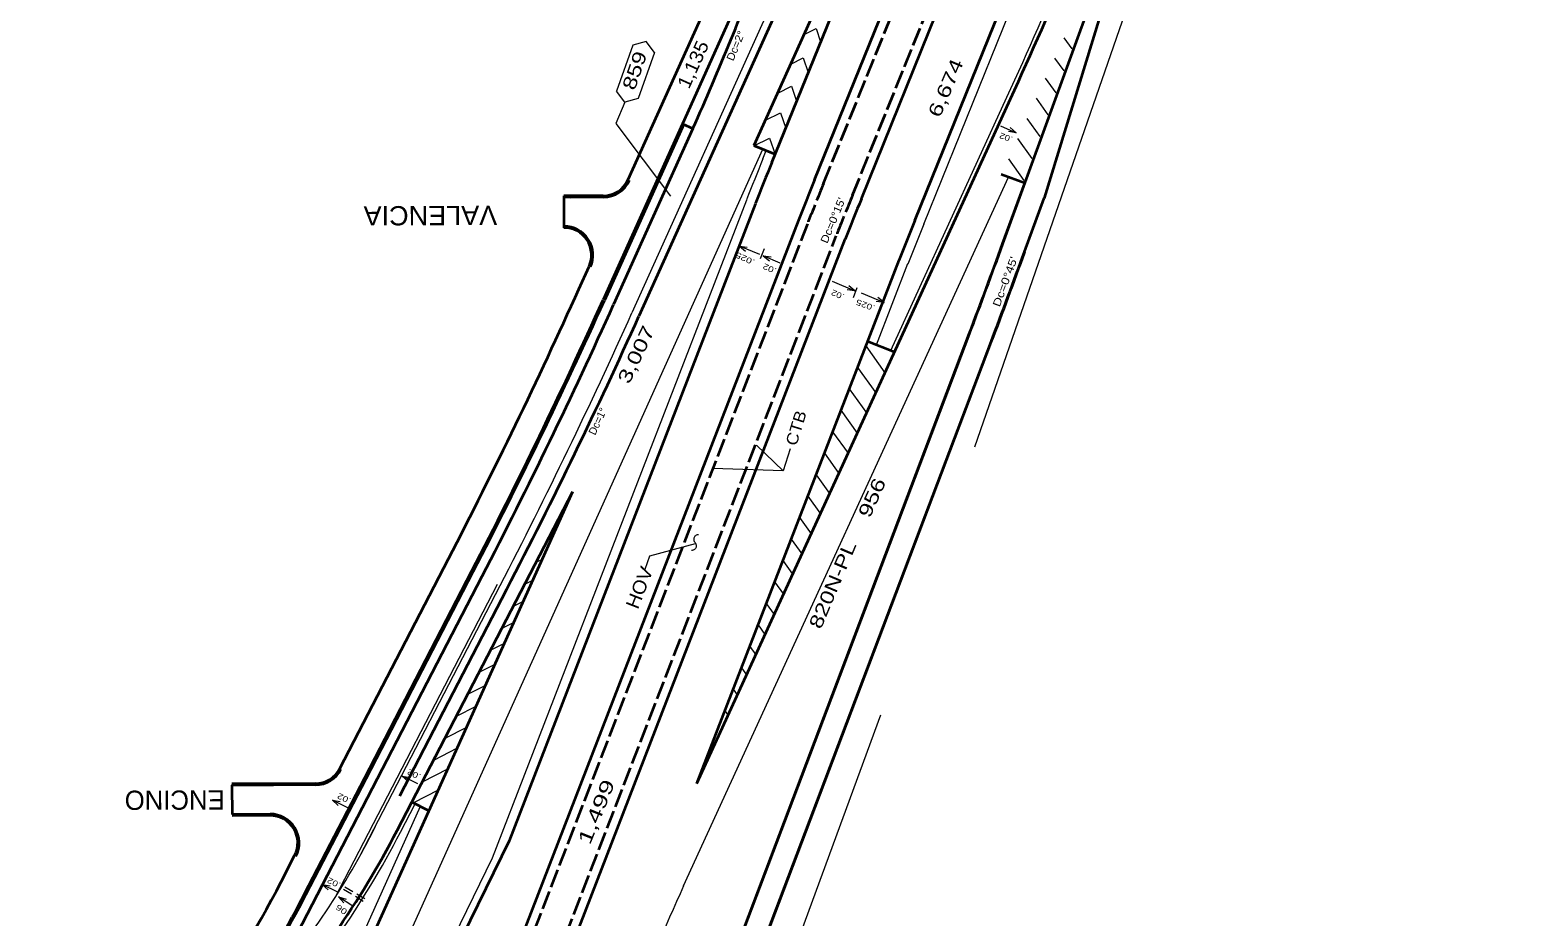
# Model space of a CAD drawing. Extents: x 2354993 to 2372084, y 6966390 to 6990057.
# Drawn here: x 2364884 to 2366452, y 6981393 to 6982315 of the extents above; entities that cross this region are included whole.
import ezdxf

# ---------------------------------------------------------------- set-up
doc = ezdxf.new("R2010")
doc.units = 0
doc.header["$LTSCALE"] = 3.2
doc.linetypes.add('LONG_DASHED', pattern=[7.5, 6, -1.5])
doc.linetypes.add('MEDIUM_DASHED', pattern=[4.5, 3, -1.5])
for name, color, linetype, lineweight in [('10', 7, 'Continuous', 13), ('12', 7, 'Continuous', 13), ('13', 7, 'Continuous', 13), ('17', 7, 'Continuous', 13), ('19', 7, 'Continuous', 13), ('2', 7, 'Continuous', 35), ('4', 7, 'Continuous', 13), ('5', 7, 'Continuous', 35), ('9', 7, 'Continuous', 13)]:
    doc.layers.add(name, color=color, linetype=linetype, lineweight=lineweight)

msp = doc.modelspace()

# ---------------------------------------------------------------- linework, layer by layer
at = {"layer": '10'}
msp.add_arc((2358740.096, 6984698.511), 7640.437, 339.24044, 339.9908, dxfattribs=at)
at = {"layer": '12', "linetype": 'MEDIUM_DASHED'}
for p, q in [((2365230.832, 6981409.397), (2365208.441, 6981422.614)), ((2365232.368, 6981411.974), (2365209.977, 6981425.191))]:
    msp.add_line(p, q, dxfattribs=at)
at = {"layer": '13'}
msp.add_line((2365510.907, 6982298.979), (2365493.918, 6982251.353), dxfattribs=at)
for points in [[(2365533.695, 6982291.446), (2365524.87, 6982302.789), (2365510.907, 6982298.979)], [(2365533.695, 6982291.446), (2365516.704, 6982243.818), (2365502.742, 6982240.009), (2365493.918, 6982251.353)], [(2365502.742, 6982240.009), (2365493.365, 6982217.721), (2365550.177, 6982142.129)], [(2365523.937, 6981754.741), (2365528.75, 6981768.443), (2365576.386, 6981781.284)], [(2365579.387, 6981790.427), (2365577.948, 6981790.249), (2365576.978, 6981789.862), (2365576.231, 6981789.374), (2365575.638, 6981788.818), (2365575.169, 6981788.207), (2365574.811, 6981787.545), (2365574.556, 6981786.837), (2365574.413, 6981786.079), (2365574.394, 6981785.266), (2365574.527, 6981784.384), (2365574.886, 6981783.403), (2365575.186, 6981782.875), (2365575.712, 6981782.213), (2365576.236, 6981781.547), (2365576.536, 6981781.022), (2365576.679, 6981780.703), (2365576.895, 6981780.039), (2365576.989, 6981779.558), (2365577.029, 6981779.157), (2365577.009, 6981778.346), (2365576.866, 6981777.588), (2365576.613, 6981776.88), (2365576.253, 6981776.219), (2365575.783, 6981775.607), (2365575.192, 6981775.05), (2365574.444, 6981774.563), (2365573.807, 6981774.281), (2365573.474, 6981774.175), (2365572.881, 6981774.048), (2365572.037, 6981773.997)]]:
    msp.add_lwpolyline(points, dxfattribs=at)
at = {"layer": '19'}
for p, q in [((2365893.323, 6982215.361), (2365909.789, 6982208.072)), ((2365909.789, 6982208.072), (2365901.562, 6982209.227)), ((2365909.789, 6982208.072), (2365903.401, 6982213.388)), ((2365621.858, 6982090.33), (2365628.356, 6982085.156)), ((2365621.858, 6982090.33), (2365630.112, 6982089.355)), ((2365642.949, 6982081.536), (2365621.858, 6982090.33)), ((2365647.522, 6982087.307), (2365643.569, 6982077.208)), ((2365646.512, 6982080.169), (2365653.01, 6982074.995)), ((2365646.512, 6982080.169), (2365654.765, 6982079.194)), ((2365664.327, 6982072.741), (2365646.512, 6982080.169)), ((2365742.024, 6982043.676), (2365733.782, 6982044.741)), ((2365740.592, 6982036.979), (2365744.357, 6982047.15)), ((2365772.228, 6982031.661), (2365763.985, 6982032.726)), ((2365271.369, 6981539.541), (2365277.566, 6981534.01)), ((2365271.369, 6981539.541), (2365279.555, 6981538.104)), ((2365287.574, 6981531.688), (2365271.369, 6981539.541)), ((2365198.647, 6981514.536), (2365204.844, 6981509.005)), ((2365198.647, 6981514.536), (2365206.833, 6981513.099)), ((2365214.852, 6981506.683), (2365198.647, 6981514.536)), ((2365188.077, 6981426.882), (2365194.274, 6981421.351)), ((2365188.077, 6981426.882), (2365196.263, 6981425.445)), ((2365204.282, 6981419.029), (2365188.077, 6981426.882)), ((2365205.079, 6981414.245), (2365210.455, 6981407.913)), ((2365205.079, 6981414.245), (2365212.989, 6981411.694)), ((2365220.047, 6981404.234), (2365205.079, 6981414.245))]:
    msp.add_line(p, q, dxfattribs=at)
for points in [[(2365718.336, 6982053.856), (2365742.024, 6982043.676), (2365735.583, 6982048.92)], [(2365748.54, 6982041.841), (2365772.228, 6982031.661), (2365765.786, 6982036.905)]]:
    msp.add_lwpolyline(points, dxfattribs=at)
at = {"layer": '2'}
for p, q in [((2365858.107, 6982773.741), (2365517.469, 6982017.581)), ((2365655.565, 6982177.229), (2365892.178, 6982761.724)), ((2365879.26, 6982733.049), (2365636.764, 6982194.747)), ((2365506.33, 6982159.631), (2365756.042, 6982713.951)), ((2365700.058, 6982159.218), (2365878.037, 6982598.874)), ((2365748.722, 6982139.518), (2365926.701, 6982579.174)), ((2365562.571, 6982217.52), (2365480.087, 6982034.421)), ((2365563.939, 6982216.904), (2365481.455, 6982033.805)), ((2365636.764, 6982194.747), (2365659.01, 6982185.741)), ((2365480.379, 6982142.597), (2365439.311, 6982142.392)), ((2365439.311, 6982142.392), (2365439.474, 6982109.426)), ((2365480.387, 6982141.097), (2365439.318, 6982140.892)), ((2365480.387, 6982141.097), (2365446.259, 6982140.927)), ((2365638.459, 6982134.483), (2365382.326, 6981472.187)), ((2365683.228, 6982117.169), (2365358.55, 6981277.634)), ((2365407.217, 6981257.934), (2365731.885, 6982097.447)), ((2365455.01, 6982045.709), (2365465.601, 6982069.22)), ((2365029.335, 6980904.779), (2365448.587, 6981835.455)), ((2365281.153, 6981512.478), (2365448.571, 6981835.42)), ((2365206.278, 6981547.302), (2365319.371, 6981765.458)), ((2365232.324, 6981537.792), (2365343.797, 6981752.824)), ((2365233.656, 6981537.102), (2365345.129, 6981752.134)), ((2365268.724, 6981518.921), (2365380.197, 6981733.953)), ((2365169.806, 6981417.192), (2365232.324, 6981537.792)), ((2365171.138, 6981416.502), (2365233.656, 6981537.102)), ((2365265.914, 6981483.077), (2365281.155, 6981512.477)), ((2365299.063, 6981503.534), (2365281.153, 6981512.478)), ((2365382.326, 6981472.187), (2365167.295, 6981031.876)), ((2365145.393, 6981429.854), (2365159.418, 6981456.908))]:
    msp.add_line(p, q, dxfattribs=at)
at = {"layer": '2', "linetype": 'LONG_DASHED'}
for p, q in [((2365709.327, 6982155.466), (2365887.306, 6982595.122)), ((2365739.453, 6982143.27), (2365917.432, 6982582.926)), ((2365692.555, 6982113.562), (2365367.877, 6981274.027)), ((2365397.89, 6981261.541), (2365722.558, 6982101.054))]:
    msp.add_line(p, q, dxfattribs=at)
at = {"layer": '2', "lineweight": 13}
msp.add_line((2365667.481, 6981856.792), (2365594.184, 6981859.199), dxfattribs=at)
at = {"layer": '2'}
msp.add_lwpolyline([(2365682.892, 6982484.609), (2365562.57, 6982217.518), (2365573.511, 6982212.589)], dxfattribs=at)
at = {"layer": '2', "lineweight": 13}
msp.add_lwpolyline([(2365674.567, 6981879.694), (2365667.481, 6981856.792), (2365639.805, 6981883.28)], dxfattribs=at)
at = {"layer": '2'}
for centre, radius, start, end in [((2362974.286, 6983383.498), 2850.789, 335.74918, 339.77145), ((2371035.303, 6979999.424), 5803.828, 157.9611, 158.41195), ((2365480.237, 6982171.096), 28.5, 270.28559, 335.74925), ((2365480.237, 6982171.096), 30, 270.28559, 335.74925), ((2371035.304, 6979999.424), 5755.828, 157.9611, 158.41275), ((2371035.303, 6979999.424), 5703.328, 157.9611, 158.4163), ((2365439.616, 6982080.926), 30, 335.74944, 90.28559), ((2365439.616, 6982080.926), 28.5, 335.74944, 90.28533), ((2360293.486, 6984370.89), 5661.078, 332.59766, 335.74922), ((2360293.489, 6984370.897), 5688.578, 332.59784, 335.74923), ((2360293.489, 6984370.897), 5690.078, 332.59784, 335.74923), ((2360293.489, 6984370.896), 5729.578, 332.59784, 335.74923), ((2364406.014, 6981928.856), 968.58, 317.77096, 332.59746), ((2364129.385, 6981956.555), 1144.416, 323.97105, 332.59766), ((2364129.386, 6981956.557), 1171.916, 321.88117, 332.59727), ((2364129.386, 6981956.557), 1173.416, 326.58947, 332.59727)]:
    msp.add_arc(centre, radius, start, end, dxfattribs=at)
at = {"layer": '2', "linetype": 'LONG_DASHED'}
for centre, radius, end in [((2371035.304, 6979999.424), 5745.828, 158.41275), ((2371035.303, 6979999.424), 5713.328, 158.4163)]:
    msp.add_arc(centre, radius, 157.9611, end, dxfattribs=at)
at = {"layer": '4'}
for p, q in [((2365850.813, 6982777.027), (2365510.175, 6982020.867)), ((2365645.882, 6982190.639), (2365062.309, 6980895.203)), ((2365646.296, 6982180.981), (2365649.742, 6982189.493)), ((2365629.132, 6982138.09), (2365364.685, 6981454.295)), ((2365201.706, 6981413.541), (2365370.432, 6981739.016)), ((2365227.335, 6981456.463), (2365373.095, 6981737.635)), ((2365290.106, 6981508.007), (2365022.191, 6980913.275)), ((2365269.466, 6981481.236), (2365284.706, 6981510.636)), ((2365364.685, 6981454.295), (2365160.333, 6981035.852))]:
    msp.add_line(p, q, dxfattribs=at)
for points in [[(2365689.17, 6982310.318), (2365701.705, 6982316.447), (2365706.351, 6982302.686)], [(2365675.236, 6982279.386), (2365688.317, 6982285.782), (2365693.406, 6982270.708)], [(2365661.728, 6982249.402), (2365676.018, 6982256.389), (2365681.289, 6982240.776)], [(2365649.056, 6982221.271), (2365664.597, 6982228.87), (2365669.996, 6982212.879)], [(2365637.054, 6982194.628), (2365653.324, 6982202.583), (2365659.01, 6982185.741)]]:
    msp.add_lwpolyline(points, dxfattribs=at)
for centre, radius, start, end in [((2371035.303, 6979999.424), 5813.828, 157.9611, 158.41195), ((2360293.489, 6984370.896), 5721.578, 332.59784, 335.74923), ((2364406.014, 6981928.856), 972.58, 317.77096, 332.59746), ((2364530.202, 6981842.504), 796.823, 319.17372, 334.00023)]:
    msp.add_arc(centre, radius, start, end, dxfattribs=at)
at = {"layer": '5'}
for p, q in [((2365804.338, 6982117.004), (2365982.317, 6982556.66)), ((2365895.848, 6982092.73), (2366007.685, 6982399.844)), ((2366008.225, 6982366.256), (2365938.683, 6982140.218)), ((2365577.516, 6981531.942), (2365903.725, 6982243.407)), ((2365573.511, 6982212.589), (2365491.028, 6982029.491)), ((2365918.836, 6982155.854), (2365894.112, 6982164.858)), ((2365918.4, 6982084.517), (2365938.683, 6982140.218)), ((2365577.516, 6981531.942), (2365787.846, 6982075.805)), ((2365338.182, 6980619.691), (2365861.11, 6981999.242)), ((2365428.134, 6980789.285), (2365883.552, 6981990.735)), ((2365755.194, 6981991.376), (2365783.175, 6981980.555)), ((2365134.648, 6981323.301), (2365354.45, 6981747.299)), ((2365181.13, 6981531.919), (2365094.158, 6981531.449)), ((2365133.831, 6981500.056), (2365094.609, 6981499.661)), ((2365133.846, 6981498.556), (2365094.624, 6981498.161))]:
    msp.add_line(p, q, dxfattribs=at)
at = {"layer": '5', "lineweight": 13}
for p, q in [((2365813.607, 6982113.252), (2365991.586, 6982552.908)), ((2366025.609, 6982341.071), (2365866.293, 6981881.435)), ((2365959.101, 6982306.746), (2365967.427, 6982295.137)), ((2365949.544, 6982285.755), (2365959.138, 6982272.376)), ((2365939.945, 6982264.82), (2365950.85, 6982249.615)), ((2365779.464, 6981981.99), (2365900.089, 6982245.074)), ((2365930.347, 6982243.886), (2365942.562, 6982226.854)), ((2365920.748, 6982222.952), (2365934.273, 6982204.093)), ((2365911.15, 6982202.018), (2365925.985, 6982181.332)), ((2365901.552, 6982181.083), (2365917.696, 6982158.571)), ((2365563.867, 6981425.395), (2365901.654, 6982162.111)), ((2365894.909, 6982093.072), (2365917.896, 6982156.197)), ((2365764.521, 6981987.769), (2365797.173, 6982072.198)), ((2365337.246, 6980620.046), (2365860.175, 6981999.596)), ((2365429.069, 6980788.933), (2365884.487, 6981990.381)), ((2365753.324, 6981986.538), (2365773.225, 6981958.787)), ((2365744.701, 6981964.243), (2365763.627, 6981937.852)), ((2365736.079, 6981941.948), (2365754.029, 6981916.918)), ((2365727.456, 6981919.652), (2365744.43, 6981895.984)), ((2365718.834, 6981897.357), (2365734.832, 6981875.05)), ((2365710.212, 6981875.062), (2365725.233, 6981854.115)), ((2365701.589, 6981852.766), (2365715.635, 6981833.181)), ((2365692.967, 6981830.471), (2365706.036, 6981812.247)), ((2365684.345, 6981808.176), (2365696.438, 6981791.312)), ((2365426.537, 6981786.508), (2365422.028, 6981784.22)), ((2365675.722, 6981785.88), (2365686.84, 6981770.378)), ((2365416.713, 6981764.7), (2365410.193, 6981761.391)), ((2365667.1, 6981763.585), (2365677.241, 6981749.444)), ((2365406.889, 6981742.892), (2365398.358, 6981738.562)), ((2365658.478, 6981741.29), (2365667.643, 6981728.51)), ((2365397.065, 6981721.084), (2365386.524, 6981715.733)), ((2365649.855, 6981718.994), (2365658.044, 6981707.575)), ((2365387.241, 6981699.275), (2365374.689, 6981692.905)), ((2365641.233, 6981696.699), (2365648.446, 6981686.641)), ((2365377.416, 6981677.467), (2365362.854, 6981670.076)), ((2365632.61, 6981674.403), (2365638.847, 6981665.707)), ((2365367.592, 6981655.659), (2365351.02, 6981647.248)), ((2365623.988, 6981652.108), (2365629.249, 6981644.772)), ((2365357.768, 6981633.851), (2365339.184, 6981624.418)), ((2365615.366, 6981629.813), (2365619.65, 6981623.838)), ((2365347.943, 6981612.041), (2365327.349, 6981601.588)), ((2365606.743, 6981607.517), (2365610.052, 6981602.904)), ((2365338.119, 6981590.233), (2365315.516, 6981578.76)), ((2365328.295, 6981568.425), (2365303.682, 6981555.931)), ((2365318.471, 6981546.617), (2365291.848, 6981533.103)), ((2365308.646, 6981524.808), (2365282.85, 6981511.713))]:
    msp.add_line(p, q, dxfattribs=at)
msp.add_lwpolyline([(2365569.779, 6981058.596), (2365647.705, 6981272.931), (2365768.875, 6981603.207)], dxfattribs=at)
at = {"layer": '5'}
msp.add_lwpolyline([(2365181.138, 6981530.419), (2365094.166, 6981529.949), (2365094.609, 6981499.661)], dxfattribs=at)
at = {"layer": '5', "lineweight": 13}
for centre, radius, start, end in [((2360717.318, 6984621.39), 5701.578, 335.3684, 338.5448), ((2371035.303, 6979999.424), 5633.328, 157.9611, 158.4163), ((2358740.096, 6984698.511), 7614.437, 339.24044, 339.9908), ((2368160.706, 6980234.736), 2856.789, 155.3684, 158.22353)]:
    msp.add_arc(centre, radius, start, end, dxfattribs=at)
at = {"layer": '5'}
for centre, radius, start, end in [((2360717.318, 6984621.39), 5705.578, 335.3684, 338.5448), ((2371035.303, 6979999.424), 5643.328, 157.9611, 158.4163), ((2358740.096, 6984698.511), 7615.437, 339.24044, 339.9908), ((2358740.096, 6984698.511), 7639.437, 339.24044, 339.9908), ((2360293.489, 6984370.895), 5700.578, 332.59784, 335.74923), ((2365180.976, 6981560.419), 28.5, 270.30961, 332.59757), ((2365180.976, 6981560.419), 30, 270.30961, 332.59757), ((2365134.133, 6981470.057), 30, 332.59791, 90.57645), ((2365134.133, 6981470.057), 28.5, 332.59791, 90.57645)]:
    msp.add_arc(centre, radius, start, end, dxfattribs=at)
at = {"layer": '9'}
msp.add_arc((2360722.521, 6984327.136), 5729.573, 359.50797, 359.50797, dxfattribs=at)

# ---------------------------------------------------------------- texts
at = {"layer": '13'}
for s, height, rotation, width, p in [('1,135', 14, 65.613, 1.1, (2365569.427, 6982252.742)), ('859', 14, 70.956, 1.3, (2365512.911, 6982251.313)), ('6,674', 14, 66.706, 1.35, (2365830.244, 6982222.869)), ('VALENCIA', 20, 180.22, 1.05, (2365369.997, 6982132.27)), ('3,007', 14, 64.566, 1.35, (2365507.227, 6981946.071)), ('CTB', 12, 72.807, 1.15, (2365681.055, 6981881.919)), ('820N-PL', 14, 67.104, 1.3, (2365706.524, 6981691.388)), ('HOV', 14, 68.713, 1.1, (2365516.323, 6981712.085)), ('1,499', 14, 67.927, 1.5, (2365466.399, 6981467.254))]:
    msp.add_text(s, height=height, rotation=rotation, dxfattribs=dict(at, width=width)).set_placement(p)
msp.add_text('ENCINO', height=20, rotation=180.22, dxfattribs=at).set_placement((2365086.671, 6981524.823))
at = {"layer": '17'}
for s, rotation, width, p in [('Dc=2°', 67.07, 1.1, (2365615.408, 6982281.992)), ("Dc=0°15'", 67.442, 1.15, (2365713.216, 6982092.416))]:
    msp.add_text(s, height=8, rotation=rotation, dxfattribs=dict(at, width=width)).set_placement(p)
msp.add_text('Dc=1°', height=8, rotation=64.778, dxfattribs=at).set_placement((2365471.842, 6981893.21))
at = {"layer": '19'}
for s, height, rotation, width, p in [('.02', 6, 160.217, 1.25, (2365906.655, 6982203.656)), ('.025', 5.999, 155.55, 1.35, (2365638.563, 6982075.684)), ("Dc=0°45'", 8, 69.681, 1.25, (2365892.488, 6982026.499)), ('.02', 6, 155.855, 1.3, (2365661.167, 6982066.71)), ('.02', 5.999, 156.311, 1.25, (2365731.75, 6982039.784)), ('.025', 6, 159.683, 1.3, (2365763.478, 6982028.252)), ('956', 14, 65.763, 1.35, (2365757.424, 6981806.828)), ('.02', 6, 154.187, 1.3, (2365291.387, 6981540.937)), ('.02', 6, 154.187, 1.3, (2365218.665, 6981515.932)), ('.02', 6, 154.187, 1.3, (2365208.095, 6981428.278)), ('.06', 6, 146.266, 1.35, (2365217.3, 6981398.427))]:
    msp.add_text(s, height=height, rotation=rotation, dxfattribs=dict(at, width=width)).set_placement(p)

doc.saveas('drawing.dxf')
